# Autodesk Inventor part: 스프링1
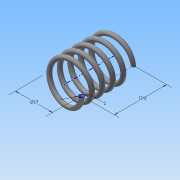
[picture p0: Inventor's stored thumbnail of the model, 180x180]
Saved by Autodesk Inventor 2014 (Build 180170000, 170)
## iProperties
Created: 2016-01
Part Number: 스프링1
Material: 강철, 탄소
Document SubType Name: Modeling
Designer: Administrator
Density: 7.87 g/cm^3
Appearance: 반연마
Mass: 6.46669 g
Surface Area: 16.7182 cm^2
Volume: 0.821689 cm^3
Author: Administrator
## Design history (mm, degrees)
sketch "스케치1"
  geometry: L1 (0, 0)-(8.5, 0); L2 (8.5, 0)-(8.5, 20.5); L3 (8.5, 20.5)-(0, 20.5); L4 (0, 20.5)-(0, 0); C1 r 1 at (8.5, 0)
  constraints: 8 end point, 2 parallel, 1 centre point, 1 coincident, 1 horizontal, 1 perpendicular
  dimensions: "d0" = 17 diameter of L2 L4; "d1" = 20.5 distance of L1.end L2.end (derived); "d2" = 2 diameter of C1
feature "코일1" pitch "d3" = 10; turns "d5" = 5; dims "d4" = 20.5 (= d1), "d6" = 0, angle "d7" = 90 deg, angle "d8" = 90 deg, "d9" = 0, "d10" = 0
node "작업 평면1"
sketch "스케치2"
  geometry: L1 (-9.5, 0)-(-7.5, 0) reference; 1 further point
  constraints: 1 horizontal alignment
extrude "돌출1" cut sketch "스케치2" distance "d12" = 10; taper "d13" = 0 deg
node "작업 평면2"
sketch "스케치3"
  geometry: L1 (-7.5, 0)-(-9.5, 0) reference; 1 further point
  constraints: 1 horizontal alignment
extrude "돌출2" cut sketch "스케치3" distance "d15" = 10; taper "d16" = 0 deg
node "솔리드1"
node "절단 모서리 투영1"
node "절단 모서리 투영2"
other parameters: "d11" = 0, "d14" = 20.5 (= d1)
